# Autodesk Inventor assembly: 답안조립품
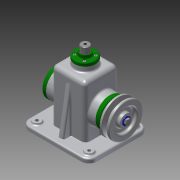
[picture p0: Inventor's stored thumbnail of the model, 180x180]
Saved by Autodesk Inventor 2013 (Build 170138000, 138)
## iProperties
Created: 2016-01
Part Number: 답안조립품
Document SubType Name: Assembly
Designer: User
Author: User
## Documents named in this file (18)
- C:\Users\User\Desktop\460126V1007\답안조립품.iam
- C:\Users\User\Desktop\460126V1007\앞커버.ipt
- C:\Users\User\Desktop\460126V1007\본체.ipt
- C:\Users\User\Desktop\460126V1007\베어링 15 x 35 x 11.ipt
- C:\Users\User\Desktop\460126V1007\오일실 15 25 7.ipt
- C:\Users\User\Desktop\460126V1007\뒤커버.ipt
- C:\Users\User\Desktop\460126V1007\편심축.ipt
- C:\Users\User\Desktop\460126V1007\멈춤링 15 x 1.ipt
- C:\Users\User\Desktop\460126V1007\볼트 M4 x 10.ipt
- C:\Users\User\Desktop\460126V1007\상부부시.ipt
- C:\Users\User\Desktop\460126V1007\볼트 M3 x 8.ipt
- C:\Users\User\Desktop\460126V1007\키 5 x 5 x 14.ipt
- C:\Users\User\Desktop\460126V1007\슬라이드바.ipt
- C:\Users\User\Desktop\460126V1007\링크.ipt
- C:\Users\User\Desktop\460126V1007\고정핀.ipt
- C:\Users\User\Desktop\460126V1007\와셔.ipt
- C:\Users\User\Desktop\460126V1007\V-벨트풀리.ipt
- C:\Users\User\Desktop\460126V1007\볼트 M6 x 12.ipt
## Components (15 placed, 5 different names)
1. 고정핀:1
2. V-벨트풀리:1
3. ISO 4018 M6 x 12:1 — 각도:1
4. ISO 4762 M4 x 10:1
5. ISO 4762 M4 x 10:3
6. ISO 4762 M4 x 10:4
7. ISO 4762 M4 x 10:5
8. ISO 4762 M4 x 10:2
9. ISO 4762 M4 x 10:6
10. ISO 4762 M4 x 10:7
11. ISO 4762 M4 x 10:8
12. ISO 4762 M3 x 8:1
13. ISO 4762 M3 x 8:2
14. ISO 4762 M3 x 8:3
15. ISO 4762 M3 x 8:4
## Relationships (1: Angle 1)
- 각도:1 [Angle]: ISO 4018 M6 x 12:1
